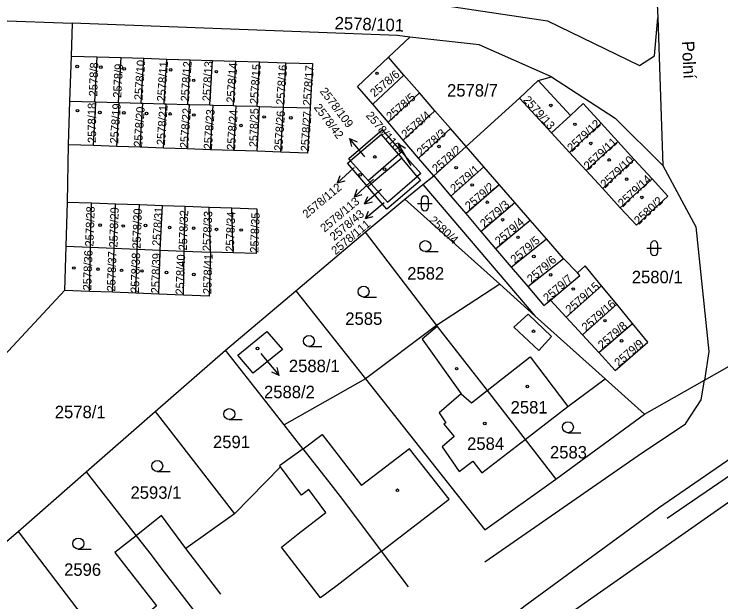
# Model space of a CAD drawing. Extents: x -527335 to -526256, y -1079142 to -1077809.
# Drawn here: x -526700.3 to -526603.7, y -1078371.4 to -1078291.1 of the extents above; entities that cross this region are included whole.
import ezdxf

# ---------------------------------------------------------------- set-up
doc = ezdxf.new("R2010")
doc.units = 0
for name, color, linetype in [('Vrstva 1', 7, 'Continuous'), ('Vrstva 2', 7, 'Continuous'), ('Vrstva 3', 7, 'Continuous'), ('Vrstva 4', 7, 'Continuous'), ('Vrstva 5', 7, 'Continuous'), ('Vrstva 7', 7, 'Continuous')]:
    doc.layers.add(name, color=color, linetype=linetype)

msp = doc.modelspace()

# ---------------------------------------------------------------- linework, layer by layer
at = {"layer": 'Vrstva 1'}
for p, q in [((-526613.4, -1078261.09), (-526612.35, -1078291.6)), ((-526720.03, -1078291.28), (-526692.39, -1078292.33)), ((-526692.39, -1078292.33), (-526692.56, -1078296.81)), ((-526612.35, -1078291.6), (-526611.66, -1078311.76)), ((-526649.16, -1078296.97), (-526646.23, -1078294.21)), ((-526692.56, -1078296.81), (-526692.76, -1078302.96)), ((-526692.56, -1078296.81), (-526688.97, -1078296.92)), ((-526689.31, -1078303.06), (-526688.97, -1078296.92)), ((-526688.97, -1078296.92), (-526685.72, -1078297.02)), ((-526686.06, -1078303.15), (-526685.72, -1078297.02)), ((-526685.72, -1078297.02), (-526682.62, -1078297.12)), ((-526682.96, -1078303.23), (-526682.62, -1078297.12)), ((-526682.62, -1078297.12), (-526679.48, -1078297.22)), ((-526679.81, -1078303.32), (-526679.48, -1078297.22)), ((-526679.48, -1078297.22), (-526676.28, -1078297.32)), ((-526647.04, -1078299.41), (-526649.16, -1078296.97)), ((-526676.61, -1078303.41), (-526676.28, -1078297.32)), ((-526676.28, -1078297.32), (-526673.23, -1078297.41)), ((-526673.56, -1078303.5), (-526673.23, -1078297.41)), ((-526673.23, -1078297.41), (-526670.03, -1078297.51)), ((-526670.36, -1078303.59), (-526670.03, -1078297.51)), ((-526670.03, -1078297.51), (-526666.78, -1078297.61)), ((-526667.12, -1078303.68), (-526666.78, -1078297.61)), ((-526666.78, -1078297.61), (-526663.18, -1078297.72)), ((-526663.52, -1078303.78), (-526663.18, -1078297.72)), ((-526647.04, -1078299.41), (-526651.3, -1078303.4)), ((-526644.92, -1078301.85), (-526647.04, -1078299.41)), ((-526631.23, -1078302.56), (-526628.69, -1078300.14)), ((-526628.69, -1078300.14), (-526626.89, -1078299.64)), ((-526624.28, -1078304.92), (-526628.69, -1078300.14)), ((-526644.92, -1078301.85), (-526649.22, -1078305.85)), ((-526642.8, -1078304.29), (-526644.92, -1078301.85)), ((-526692.76, -1078302.96), (-526692.95, -1078308.93)), ((-526692.76, -1078302.96), (-526689.31, -1078303.06)), ((-526689.49, -1078309.05), (-526689.16, -1078303.06)), ((-526689.31, -1078303.06), (-526689.16, -1078303.06)), ((-526689.16, -1078303.06), (-526686.06, -1078303.15)), ((-526638.55, -1078309.17), (-526631.23, -1078302.56)), ((-526631.23, -1078302.56), (-526626.89, -1078307.29)), ((-526686.29, -1078309.16), (-526685.96, -1078303.15)), ((-526686.06, -1078303.15), (-526685.96, -1078303.15)), ((-526685.96, -1078303.15), (-526682.96, -1078303.23)), ((-526683.1, -1078309.27), (-526682.76, -1078303.24)), ((-526682.96, -1078303.23), (-526682.76, -1078303.24)), ((-526682.76, -1078303.24), (-526679.81, -1078303.32)), ((-526679.9, -1078309.38), (-526679.56, -1078303.33)), ((-526679.81, -1078303.32), (-526679.56, -1078303.33)), ((-526679.56, -1078303.33), (-526676.61, -1078303.41)), ((-526676.7, -1078309.5), (-526676.36, -1078303.42)), ((-526676.61, -1078303.41), (-526676.36, -1078303.42)), ((-526676.36, -1078303.42), (-526673.56, -1078303.5)), ((-526673.56, -1078303.5), (-526673.14, -1078303.51)), ((-526673.48, -1078309.61), (-526673.14, -1078303.51)), ((-526673.14, -1078303.51), (-526670.36, -1078303.59)), ((-526670.36, -1078303.59), (-526669.96, -1078303.6)), ((-526670.3, -1078309.72), (-526669.96, -1078303.6)), ((-526669.96, -1078303.6), (-526667.12, -1078303.68)), ((-526667.12, -1078303.68), (-526666.77, -1078303.69)), ((-526667.11, -1078309.83), (-526666.77, -1078303.69)), ((-526666.77, -1078303.69), (-526663.52, -1078303.78)), ((-526663.86, -1078309.94), (-526663.52, -1078303.78)), ((-526663.52, -1078303.78), (-526659.87, -1078303.88)), ((-526649.22, -1078305.85), (-526651.3, -1078303.4)), ((-526642.8, -1078304.29), (-526647.14, -1078308.3)), ((-526640.68, -1078306.73), (-526642.8, -1078304.29)), ((-526624.28, -1078304.92), (-526626.89, -1078307.29)), ((-526647.14, -1078308.3), (-526649.22, -1078305.85)), ((-526620.09, -1078305.97), (-526624.41, -1078309.98)), ((-526617.79, -1078308.48), (-526620.09, -1078305.97)), ((-526640.68, -1078306.73), (-526645.06, -1078310.75)), ((-526638.55, -1078309.17), (-526640.68, -1078306.73)), ((-526626.89, -1078307.29), (-526624.41, -1078309.98)), ((-526645.06, -1078310.75), (-526647.14, -1078308.3)), ((-526617.79, -1078308.48), (-526622.14, -1078312.45)), ((-526615.55, -1078310.93), (-526617.79, -1078308.48)), ((-526692.95, -1078308.93), (-526693.08, -1078316.77)), ((-526689.49, -1078309.05), (-526692.95, -1078308.93)), ((-526686.29, -1078309.16), (-526689.49, -1078309.05)), ((-526683.1, -1078309.27), (-526686.29, -1078309.16)), ((-526679.9, -1078309.38), (-526683.1, -1078309.27)), ((-526676.7, -1078309.5), (-526679.9, -1078309.38)), ((-526673.48, -1078309.61), (-526676.7, -1078309.5)), ((-526670.3, -1078309.72), (-526673.48, -1078309.61)), ((-526667.11, -1078309.83), (-526670.3, -1078309.72)), ((-526663.86, -1078309.94), (-526667.11, -1078309.83)), ((-526642.98, -1078313.2), (-526638.55, -1078309.17)), ((-526636.1, -1078311.97), (-526638.55, -1078309.17)), ((-526651.94, -1078313.8), (-526647.8, -1078310.22)), ((-526647.34, -1078310.76), (-526651.51, -1078314.29)), ((-526647.8, -1078310.22), (-526647.4, -1078309.88)), ((-526647.8, -1078310.22), (-526647.34, -1078310.76)), ((-526645.22, -1078313.27), (-526647.34, -1078310.76)), ((-526642.98, -1078313.2), (-526645.06, -1078310.75)), ((-526624.41, -1078309.98), (-526622.14, -1078312.45)), ((-526654.33, -1078311.11), (-526651.94, -1078313.8)), ((-526619.86, -1078314.93), (-526615.55, -1078310.93)), ((-526613.1, -1078313.61), (-526615.55, -1078310.93)), ((-526640.62, -1078315.97), (-526636.1, -1078311.97)), ((-526634.01, -1078314.38), (-526636.1, -1078311.97)), ((-526622.14, -1078312.45), (-526619.86, -1078314.93)), ((-526644.44, -1078314.38), (-526642.98, -1078313.2)), ((-526642.98, -1078313.2), (-526640.62, -1078315.97)), ((-526617.46, -1078317.54), (-526613.1, -1078313.61)), ((-526651.51, -1078314.29), (-526651.98, -1078314.69)), ((-526651.51, -1078314.29), (-526651.94, -1078313.8)), ((-526646.9, -1078316.38), (-526644.44, -1078314.38)), ((-526644.44, -1078314.38), (-526629.16, -1078332.29)), ((-526638.6, -1078318.35), (-526634.01, -1078314.38)), ((-526631.88, -1078316.82), (-526634.01, -1078314.38)), ((-526619.86, -1078314.93), (-526617.46, -1078317.54)), ((-526652.33, -1078320.86), (-526646.9, -1078316.38)), ((-526633.94, -1078328), (-526646.9, -1078316.38)), ((-526640.62, -1078315.97), (-526638.6, -1078318.35)), ((-526693.08, -1078316.77), (-526693.26, -1078322.79)), ((-526693.08, -1078316.77), (-526689.74, -1078316.89)), ((-526689.91, -1078322.93), (-526689.74, -1078316.89)), ((-526689.74, -1078316.89), (-526686.49, -1078317)), ((-526686.65, -1078323.07), (-526686.49, -1078317)), ((-526686.49, -1078317), (-526683.2, -1078317.11)), ((-526683.5, -1078323.2), (-526683.2, -1078317.11)), ((-526683.2, -1078317.11), (-526680.06, -1078317.22)), ((-526680.35, -1078323.34), (-526680.06, -1078317.22)), ((-526680.06, -1078317.22), (-526676.96, -1078317.33)), ((-526677.1, -1078323.48), (-526676.96, -1078317.33)), ((-526676.96, -1078317.33), (-526673.67, -1078317.44)), ((-526673.67, -1078317.44), (-526670.57, -1078317.55)), ((-526673.47, -1078323.63), (-526673.67, -1078317.44)), ((-526670.39, -1078323.7), (-526670.57, -1078317.55)), ((-526636.54, -1078320.77), (-526631.88, -1078316.82)), ((-526629.77, -1078319.23), (-526631.88, -1078316.82)), ((-526638.6, -1078318.35), (-526636.54, -1078320.77)), ((-526634.51, -1078323.15), (-526629.77, -1078319.23)), ((-526627.56, -1078321.77), (-526629.77, -1078319.23)), ((-526661.84, -1078328.88), (-526652.33, -1078320.86)), ((-526652.33, -1078320.86), (-526642.59, -1078333.62)), ((-526636.54, -1078320.77), (-526634.51, -1078323.15)), ((-526632.38, -1078325.66), (-526627.56, -1078321.77)), ((-526625.21, -1078324.46), (-526627.56, -1078321.77)), ((-526693.26, -1078322.79), (-526693.43, -1078328.83)), ((-526693.26, -1078322.79), (-526689.91, -1078322.93)), ((-526690.03, -1078328.97), (-526689.91, -1078322.93)), ((-526689.91, -1078322.93), (-526686.65, -1078323.07)), ((-526686.87, -1078329.1), (-526686.65, -1078323.07)), ((-526686.65, -1078323.07), (-526683.5, -1078323.2)), ((-526683.71, -1078329.22), (-526683.5, -1078323.2)), ((-526683.5, -1078323.2), (-526680.35, -1078323.34)), ((-526680.56, -1078329.34), (-526680.35, -1078323.34)), ((-526680.35, -1078323.34), (-526677.1, -1078323.48)), ((-526634.51, -1078323.15), (-526632.38, -1078325.66)), ((-526677.2, -1078329.49), (-526677.1, -1078323.48)), ((-526677.1, -1078323.48), (-526673.47, -1078323.63)), ((-526670.39, -1078323.7), (-526673.47, -1078323.63)), ((-526630.12, -1078328.32), (-526625.21, -1078324.46)), ((-526623.32, -1078326.45), (-526625.21, -1078324.46)), ((-526632.38, -1078325.66), (-526630.12, -1078328.32)), ((-526633.94, -1078328), (-526642.59, -1078333.62)), ((-526629.16, -1078332.29), (-526633.94, -1078328)), ((-526624.86, -1078332.51), (-526620.02, -1078328.21)), ((-526617.96, -1078330.71), (-526620.02, -1078328.21)), ((-526693.43, -1078328.83), (-526701.71, -1078337.73)), ((-526690.03, -1078328.97), (-526693.43, -1078328.83)), ((-526686.87, -1078329.1), (-526690.03, -1078328.97)), ((-526683.71, -1078329.22), (-526686.87, -1078329.1)), ((-526671.45, -1078336.99), (-526661.84, -1078328.88)), ((-526661.84, -1078328.88), (-526652.31, -1078340.92)), ((-526680.56, -1078329.34), (-526683.71, -1078329.22)), ((-526677.2, -1078329.49), (-526680.56, -1078329.34)), ((-526627.02, -1078330.16), (-526624.86, -1078332.51)), ((-526617.96, -1078330.71), (-526622.65, -1078334.92)), ((-526615.79, -1078333.35), (-526617.96, -1078330.71)), ((-526629.16, -1078332.29), (-526619.54, -1078340.92)), ((-526624.86, -1078332.51), (-526622.65, -1078334.92)), ((-526642.59, -1078333.62), (-526652.31, -1078340.92)), ((-526620.42, -1078337.34), (-526615.79, -1078333.35)), ((-526622.65, -1078334.92), (-526620.42, -1078337.34)), ((-526681.04, -1078345.37), (-526671.45, -1078336.99)), ((-526663.41, -1078347.2), (-526671.45, -1078336.99)), ((-526652.31, -1078340.92), (-526663.41, -1078347.2)), ((-526652.31, -1078340.92), (-526635.98, -1078361.55)), ((-526619.54, -1078340.92), (-526614.17, -1078345.74)), ((-526614.17, -1078345.74), (-526605.97, -1078341.1)), ((-526690.48, -1078353.62), (-526681.04, -1078345.37)), ((-526681.04, -1078345.37), (-526670.21, -1078359.37)), ((-526626.29, -1078354.62), (-526614.17, -1078345.74)), ((-526630.48, -1078349.21), (-526626.29, -1078354.62)), ((-526699.79, -1078361.79), (-526690.48, -1078353.62)), ((-526690.48, -1078353.62), (-526683.67, -1078362.36)), ((-526635.98, -1078361.55), (-526626.29, -1078354.62)), ((-526714.46, -1078374.28), (-526699.79, -1078361.79)), ((-526699.79, -1078361.79), (-526691.04, -1078373.25))]:
    msp.add_line(p, q, dxfattribs=at)
for points in [[(-526695.92, -1078285.82), (-526696.17, -1078286.6), (-526641.44, -1078289.9), (-526627.42, -1078292.02), (-526614.86, -1078298.09), (-526612.81, -1078296.77), (-526612.35, -1078291.6)], [(-526646.23, -1078294.21), (-526647.91, -1078294.02), (-526692.39, -1078292.33)], [(-526626.89, -1078299.64), (-526636.74, -1078295.3), (-526646.23, -1078294.21)], [(-526651.3, -1078303.4), (-526653.38, -1078300.95), (-526649.16, -1078296.97)], [(-526663.18, -1078297.72), (-526659.54, -1078297.84), (-526659.87, -1078303.88)], [(-526626.89, -1078299.64), (-526618.17, -1078305.28), (-526611.66, -1078311.76)], [(-526659.87, -1078303.88), (-526660.21, -1078310.07), (-526663.86, -1078309.94)], [(-526620.09, -1078305.97), (-526622.54, -1078303.29), (-526624.28, -1078304.92)], [(-526654.33, -1078311.11), (-526654.59, -1078310.82), (-526650.04, -1078306.89), (-526647.4, -1078309.88)], [(-526647.8, -1078310.22), (-526650.1, -1078307.51), (-526654.33, -1078311.11)], [(-526647.4, -1078309.88), (-526644.75, -1078312.86), (-526645.22, -1078313.27)], [(-526651.98, -1078314.69), (-526654.74, -1078311.46), (-526654.33, -1078311.11)], [(-526611.66, -1078311.76), (-526607.16, -1078320.16), (-526605.36, -1078337.18), (-526605.97, -1078341.1)], [(-526645.22, -1078313.27), (-526644.77, -1078313.8), (-526649.38, -1078317.72), (-526651.98, -1078314.69)], [(-526651.51, -1078314.29), (-526649.29, -1078316.79), (-526645.22, -1078313.27)], [(-526613.1, -1078313.61), (-526610.95, -1078315.97), (-526615.26, -1078319.93), (-526617.46, -1078317.54)], [(-526670.57, -1078317.55), (-526667.15, -1078317.67), (-526667.26, -1078323.78), (-526670.39, -1078323.7)], [(-526673.47, -1078323.63), (-526673.67, -1078329.63), (-526677.2, -1078329.49)], [(-526538.39, -1078327.72), (-526540.03, -1078327.15), (-526546.04, -1078326.1), (-526550.79, -1078326.44), (-526558.7, -1078329.17), (-526588.71, -1078343.39), (-526596.49, -1078347.76), (-526612.22, -1078358.58), (-526630.45, -1078371.95), (-526674.07, -1078406.52), (-526700.09, -1078429.86), (-526748.62, -1078475.19)], [(-526620.02, -1078328.21), (-526622.27, -1078325.47), (-526623.32, -1078326.45)], [(-526627.02, -1078330.16), (-526623.01, -1078326.8), (-526623.32, -1078326.45)], [(-526630.12, -1078328.32), (-526627.91, -1078330.91), (-526627.02, -1078330.16)], [(-526642.59, -1078333.62), (-526642.49, -1078333.75), (-526635.67, -1078342.52), (-526630.48, -1078349.21)], [(-526620.42, -1078337.34), (-526618.18, -1078339.77), (-526613.7, -1078335.9), (-526615.79, -1078333.35)], [(-526663.65, -1078336.93), (-526667.65, -1078340.17), (-526669.74, -1078337.68), (-526665.81, -1078334.44), (-526663.65, -1078336.93)], [(-526605.97, -1078341.1), (-526595.52, -1078335.19), (-526593.56, -1078334.08)], [(-526630.48, -1078349.21), (-526624.62, -1078344.7), (-526619.54, -1078340.92)], [(-526660.83, -1078350.48), (-526661.12, -1078350.11), (-526663.41, -1078347.2)], [(-526660.83, -1078350.48), (-526664.04, -1078352.82), (-526663.93, -1078352.97), (-526670.21, -1078359.37)], [(-526646.41, -1078369.36), (-526650.13, -1078364.49), (-526655.4, -1078357.43), (-526656.98, -1078355.37), (-526660.83, -1078350.48)], [(-526634.47, -1078380.43), (-526629.02, -1078376.22), (-526594.89, -1078352.31), (-526594.34, -1078352)], [(-526670.21, -1078359.37), (-526676.87, -1078364.1), (-526680.17, -1078359.6), (-526683.67, -1078362.36)], [(-526683.67, -1078362.36), (-526686.57, -1078364.65), (-526680.89, -1078371.93), (-526687.64, -1078377.71)], [(-526683.67, -1078362.36), (-526681.62, -1078364.99), (-526680.27, -1078366.73), (-526675.48, -1078372.93), (-526670.1, -1078379.88), (-526669.15, -1078381.11), (-526668.66, -1078381.74), (-526666.21, -1078384.72)]]:
    msp.add_lwpolyline(points, dxfattribs=at)
at = {"layer": 'Vrstva 3'}
for p, q in [((-526644.691, -1078316.441), (-526644.691, -1078317.442)), ((-526643.689, -1078317.442), (-526643.689, -1078316.441)), ((-526645.191, -1078316.941), (-526643.189, -1078316.941)), ((-526613.821, -1078323.081), (-526611.819, -1078323.081)), ((-526613.321, -1078322.581), (-526613.321, -1078323.582)), ((-526612.319, -1078323.582), (-526612.319, -1078322.581)), ((-526644.123, -1078323.54), (-526642.373, -1078323.54)), ((-526652.563, -1078329.75), (-526650.813, -1078329.75)), ((-526660.033, -1078336.5), (-526658.283, -1078336.5)), ((-526670.923, -1078346.49), (-526669.173, -1078346.49)), ((-526624.623, -1078348.28), (-526622.873, -1078348.28)), ((-526680.773, -1078353.58), (-526679.023, -1078353.58)), ((-526691.563, -1078364.18), (-526689.813, -1078364.18))]:
    msp.add_line(p, q, dxfattribs=at)
for centre in [(-526644.123, -1078322.79), (-526652.563, -1078329), (-526660.033, -1078335.75), (-526670.923, -1078345.74), (-526624.623, -1078347.53), (-526680.773, -1078352.83), (-526691.563, -1078363.43)]:
    msp.add_circle(centre, 0.75, dxfattribs=at)
for centre, start, end in [((-526644.19, -1078316.441), 0, 180), ((-526644.19, -1078317.441), 180, 359.98789), ((-526612.82, -1078322.581), 0, 180), ((-526612.82, -1078323.581), 180, 359.98789)]:
    msp.add_arc(centre, 0.5, start, end, dxfattribs=at)
at = {"layer": 'Vrstva 4'}
for p, q in [((-526632.02, -1078333.85), (-526630.07, -1078332.1)), ((-526630.07, -1078332.1), (-526626.89, -1078335.15)), ((-526642.49, -1078333.75), (-526644.53, -1078335.48)), ((-526628.6, -1078337.05), (-526632.02, -1078333.85)), ((-526644.53, -1078335.48), (-526639.22, -1078342.99)), ((-526626.89, -1078335.15), (-526628.6, -1078337.05)), ((-526635.67, -1078342.52), (-526629.79, -1078337.93)), ((-526629.79, -1078337.93), (-526624.62, -1078344.7)), ((-526606.39, -1078343.8), (-526605.97, -1078341.1)), ((-526637.83, -1078344.21), (-526635.67, -1078342.52)), ((-526639.22, -1078342.99), (-526642.22, -1078345.58)), ((-526639.22, -1078342.99), (-526637.83, -1078344.21)), ((-526608.53, -1078347.08), (-526606.39, -1078343.8)), ((-526642.22, -1078345.58), (-526641.31, -1078346.93)), ((-526641.31, -1078346.93), (-526641.57, -1078347.13)), ((-526641.57, -1078347.13), (-526640.18, -1078348.82)), ((-526615, -1078351.38), (-526608.53, -1078347.08)), ((-526660.83, -1078350.48), (-526658.21, -1078348.55)), ((-526658.21, -1078348.55), (-526652.85, -1078355.49)), ((-526640.18, -1078348.82), (-526641.81, -1078350.21)), ((-526636.41, -1078353.77), (-526630.48, -1078349.21)), ((-526641.81, -1078350.21), (-526639.49, -1078353.6)), ((-526595.86, -1078349.62), (-526611.05, -1078360)), ((-526646.28, -1078350.48), (-526652.85, -1078355.49)), ((-526640.86, -1078357.35), (-526646.28, -1078350.48)), ((-526635.99, -1078365.95), (-526615, -1078351.38)), ((-526639.49, -1078353.6), (-526637.62, -1078352.18)), ((-526637.62, -1078352.18), (-526636.41, -1078353.77)), ((-526661.04, -1078356.81), (-526663.93, -1078352.97)), ((-526650.13, -1078364.49), (-526640.86, -1078357.35)), ((-526672.09, -1078370.33), (-526676.87, -1078364.1))]:
    msp.add_line(p, q, dxfattribs=at)
msp.add_lwpolyline([(-526650.13, -1078364.49), (-526656.19, -1078369.16), (-526658.45, -1078370.87), (-526663.78, -1078363.94), (-526661.51, -1078362.09), (-526657.71, -1078359.2), (-526660.06, -1078356.04), (-526661.04, -1078356.81)], dxfattribs=at)
at = {"layer": 'Vrstva 5'}
for centre in [(-526691.717, -1078298.239), (-526688.477, -1078298.339), (-526685.287, -1078298.559), (-526678.937, -1078298.699), (-526672.687, -1078298.949), (-526650.727, -1078299.179), (-526675.787, -1078300.129), (-526626.957, -1078303.559), (-526691.667, -1078304.269), (-526688.617, -1078304.519), (-526685.337, -1078304.569), (-526682.227, -1078304.669), (-526679.017, -1078304.719), (-526675.767, -1078304.869), (-526666.147, -1078305.139), (-526662.517, -1078305.249), (-526623.667, -1078306.149), (-526669.327, -1078306.309), (-526621.507, -1078308.749), (-526642.247, -1078309.169), (-526651.027, -1078310.599), (-526618.977, -1078311.009), (-526649.697, -1078312.279), (-526639.897, -1078312.069), (-526653.027, -1078313.039), (-526616.597, -1078313.629), (-526637.707, -1078314.429), (-526635.647, -1078316.789), (-526614.507, -1078316.129), (-526633.547, -1078319.179), (-526688.587, -1078319.919), (-526685.417, -1078320.039), (-526682.381, -1078319.977), (-526679.077, -1078320.239), (-526675.797, -1078320.339), (-526672.667, -1078320.499), (-526669.307, -1078320.579), (-526631.457, -1078321.589), (-526629.287, -1078324.209), (-526692.167, -1078325.779), (-526688.867, -1078325.939), (-526685.647, -1078326.089), (-526682.857, -1078326.179), (-526679.507, -1078326.399), (-526675.767, -1078326.659), (-526626.977, -1078326.709), (-526623.897, -1078328.649), (-526619.557, -1078332.979), (-526629.337, -1078334.419), (-526617.287, -1078335.729), (-526667.067, -1078336.769), (-526639.837, -1078339.529), (-526630.177, -1078341.969), (-526635.997, -1078347.029), (-526647.937, -1078356.149)]:
    msp.add_circle(centre, 0.175, dxfattribs=at)
at = {"layer": 'Vrstva 7'}
for p, q in [((-526652.54, -1078310.4), (-526654.469, -1078308.101)), ((-526654.469, -1078308.101), (-526653.442, -1078308.546)), ((-526654.469, -1078308.101), (-526654.209, -1078309.19)), ((-526646.27, -1078311.39), (-526647.77, -1078308.791)), ((-526647.77, -1078308.791), (-526646.836, -1078309.408)), ((-526647.77, -1078308.791), (-526647.703, -1078309.909)), ((-526652.37, -1078310.6), (-526652.54, -1078310.4)), ((-526646.04, -1078311.79), (-526646.27, -1078311.39)), ((-526653.92, -1078312.15), (-526656.15, -1078314.158)), ((-526653.85, -1078312.08), (-526653.92, -1078312.15)), ((-526656.15, -1078314.158), (-526655.741, -1078313.116)), ((-526651.22, -1078313.64), (-526651.63, -1078314.02)), ((-526656.15, -1078314.158), (-526655.071, -1078313.86)), ((-526651.63, -1078314.02), (-526653.825, -1078316.067)), ((-526653.825, -1078316.067), (-526653.434, -1078315.017)), ((-526650.16, -1078315.05), (-526652.425, -1078317.019)), ((-526650.11, -1078315.01), (-526650.16, -1078315.05)), ((-526653.825, -1078316.067), (-526652.751, -1078315.75)), ((-526652.425, -1078317.019), (-526651.998, -1078315.984)), ((-526652.425, -1078317.019), (-526651.341, -1078316.74)), ((-526650.02, -1078317.09), (-526652.319, -1078319.019)), ((-526649.74, -1078316.86), (-526650.02, -1078317.09)), ((-526652.319, -1078319.019), (-526651.874, -1078317.992)), ((-526652.319, -1078319.019), (-526651.23, -1078318.759)), ((-526666.61, -1078337.48), (-526666.03, -1078338.17)), ((-526666.03, -1078338.17), (-526664.101, -1078340.469)), ((-526664.101, -1078340.469), (-526664.361, -1078339.38)), ((-526664.101, -1078340.469), (-526665.128, -1078340.024))]:
    msp.add_line(p, q, dxfattribs=at)

# ---------------------------------------------------------------- texts
at = {"layer": 'Vrstva 2'}
for s, height, rotation, p in [('2578/101', 1.7, 358, (-526656.539, -1078293.139)), ('2578/8', 1.139, 88, (-526688.988, -1078302.353)), ('2578/9', 1.139, 87, (-526685.697, -1078302.541)), ('2578/10', 1.14, 86, (-526682.791, -1078302.889)), ('2578/11', 1.14, 86, (-526679.681, -1078303.069)), ('2578/12', 1.14, 86, (-526676.441, -1078303.069)), ('2578/13', 1.139, 87, (-526673.465, -1078303.037)), ('2578/14', 1.14, 86, (-526670.191, -1078303.249)), ('2578/15', 1.14, 86, (-526666.991, -1078303.429)), ('2578/16', 1.14, 86, (-526663.391, -1078303.529)), ('2578/17', 1.14, 86, (-526659.741, -1078303.629)), ('2578/6', 1.139, 40, (-526651.08, -1078302.489)), ('2578/109', 1.14, 307, (-526658.605, -1078301.643)), ('2578/5', 1.14, 41, (-526648.866, -1078305.68)), ('2579/13', 1.14, 312, (-526630.823, -1078302.871)), ('2578/18', 1.139, 90, (-526689.13, -1078308.701)), ('2578/19', 1.14, 86, (-526686.121, -1078308.819)), ('2578/20', 1.14, 86, (-526682.861, -1078309.269)), ('2578/21', 1.14, 86, (-526679.731, -1078309.039)), ('2578/22', 1.14, 86, (-526676.551, -1078309.459)), ('2578/25', 1.1, 88, (-526667.107, -1078309.271)), ('2578/42', 1.14, 307, (-526659.425, -1078303.843)), ('2578/23', 1.14, 86, (-526673.301, -1078309.619)), ('2578/24', 1.14, 86, (-526670.141, -1078309.689)), ('2578/26', 1.14, 86, (-526663.671, -1078309.819)), ('2578/27', 1.14, 86, (-526660.041, -1078309.889)), ('2578/110', 1.14, 310, (-526652.326, -1078304.966)), ('2578/4', 1.14, 41, (-526646.786, -1078308.13)), ('2579/12', 1.14, 43, (-526624.091, -1078309.976)), ('2578/3', 1.14, 41, (-526644.706, -1078310.58)), ('2579/11', 1.14, 43, (-526621.821, -1078312.446)), ('2578/2', 1.14, 41, (-526642.596, -1078312.83)), ('2579/10', 1.14, 43, (-526619.541, -1078314.926)), ('2579/1', 1.14, 41, (-526640.116, -1078315.53)), ('2579/14', 1.14, 43, (-526617.141, -1078317.536)), ('2578/112', 1.14, 40, (-526660.323, -1078319.036)), ('2579/2', 1.14, 41, (-526638.096, -1078317.91)), ('2578/113', 1.14, 40, (-526657.893, -1078320.946)), ('2579/3', 1.14, 41, (-526636.036, -1078320.33)), ('2580/2', 1.14, 43, (-526614.941, -1078319.926)), ('2578/28', 1.14, 88, (-526689.5, -1078322.869)), ('2578/29', 1.14, 88, (-526686.22, -1078322.999)), ('2578/31', 1.1, 86, (-526680.374, -1078322.785)), ('2578/30', 1.14, 88, (-526683.06, -1078323.159)), ('2578/32', 1.14, 88, (-526676.72, -1078323.399)), ('2578/33', 1.14, 88, (-526673.44, -1078323.509)), ('2578/34', 1.14, 88, (-526670.3, -1078323.589)), ('2578/35', 1.14, 88, (-526666.95, -1078323.719)), ('2578/43', 1.14, 40, (-526656.593, -1078322.116)), ('2578/111', 1.14, 40, (-526656.393, -1078324.036)), ('2580/4', 1.14, 317, (-526643.678, -1078319.386)), ('2579/4', 1.14, 41, (-526634.006, -1078322.71)), ('2579/5', 1.14, 41, (-526631.876, -1078325.22)), ('2578/36', 1.14, 88, (-526689.8, -1078328.869)), ('2578/37', 1.14, 88, (-526686.53, -1078329.009)), ('2578/38', 1.14, 88, (-526683.29, -1078329.209)), ('2578/39', 1.14, 88, (-526680.49, -1078329.269)), ('2578/40', 1.14, 88, (-526677.14, -1078329.439)), ('2578/41', 1.14, 88, (-526673.39, -1078329.369)), ('2579/6', 1.14, 41, (-526629.616, -1078327.88)), ('2579/7', 1.14, 41, (-526627.406, -1078330.47)), ('2579/15', 1.14, 41, (-526624.356, -1078332.07)), ('2579/16', 1.14, 41, (-526622.146, -1078334.48)), ('2579/8', 1.14, 41, (-526619.916, -1078336.9)), ('2579/9', 1.14, 41, (-526617.676, -1078339.33))]:
    msp.add_text(s, height=height, rotation=rotation, dxfattribs=at).set_placement(p)
for s, p in [('2578/7', (-526641.15, -1078302.35)), ('2582', (-526646.6, -1078327.36)), ('2580/1', (-526615.89, -1078327.86)), ('2585', (-526655.06, -1078333.55)), ('2588/1', (-526662.775, -1078340.01)), ('2588/2', (-526666.175, -1078343.57)), ('2578/1', (-526694.78, -1078346.3)), ('2581', (-526632.459, -1078345.66)), ('2591', (-526673.15, -1078350.39)), ('2584', (-526638.41, -1078350.63)), ('2583', (-526627.079, -1078351.8)), ('2593/1', (-526684.43, -1078357.31)), ('2596', (-526693.507, -1078367.84))]:
    msp.add_text(s, height=1.7, dxfattribs=at).set_placement(p)
at = {"layer": 'Vrstva 7'}
msp.add_text('Polní', height=1.7, rotation=273, dxfattribs=at).set_placement((-526609.058, -1078294.794))

doc.saveas('drawing.dxf')
